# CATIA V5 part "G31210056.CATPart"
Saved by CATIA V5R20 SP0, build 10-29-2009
Part number: G31210056
Revision: 8
Definition: design
Nomenclature: G31210056
Source: made
Description: NOT SPECIFIED
Bounding box of the stored display mesh (mm): x -5 to 56, y -8 to 8, z -8 to 8
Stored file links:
  C:\Users\Raffaele\Desktop\3D X SITO CF\BOLEX\23-BUSH REF 312\G31210056.CATPart
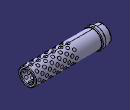
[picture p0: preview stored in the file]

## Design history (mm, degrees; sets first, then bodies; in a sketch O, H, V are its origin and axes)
Body1 "MANIFOLD_SOLID_BREP #12359" (main body)
  Solid1: solid without history
Body2 "MANIFOLD_SOLID_BREP #12502"
  Solid2: solid without history
Body3 "MANIFOLD_SOLID_BREP #12645"
  Solid3: solid without history
Body4 "MANIFOLD_SOLID_BREP #12788"
  Solid4: solid without history
Body5 "MANIFOLD_SOLID_BREP #12931"
  Solid5: solid without history
Body6 "MANIFOLD_SOLID_BREP #13076"
  Solid6: solid without history
Body7 "MANIFOLD_SOLID_BREP #13221"
  Solid7: solid without history
Body8 "MANIFOLD_SOLID_BREP #13366"
  Solid8: solid without history
Body9 "MANIFOLD_SOLID_BREP #13511"
  Solid9: solid without history
Body10 "MANIFOLD_SOLID_BREP #13656"
  Solid10: solid without history
Body11 "MANIFOLD_SOLID_BREP #13801"
  Solid11: solid without history
Body12 "MANIFOLD_SOLID_BREP #13946"
  Solid12: solid without history
Body13 "MANIFOLD_SOLID_BREP #14091"
  Solid13: solid without history
Body14 "MANIFOLD_SOLID_BREP #14236"
  Solid14: solid without history
Body15 "MANIFOLD_SOLID_BREP #14381"
  Solid15: solid without history
Body16 "MANIFOLD_SOLID_BREP #14526"
  Solid16: solid without history
Body17 "MANIFOLD_SOLID_BREP #14671"
  Solid17: solid without history
Body18 "MANIFOLD_SOLID_BREP #14816"
  Solid18: solid without history
Body19 "MANIFOLD_SOLID_BREP #14961"
  Solid19: solid without history
Body20 "MANIFOLD_SOLID_BREP #15106"
  Solid20: solid without history
Body21 "MANIFOLD_SOLID_BREP #15251"
  Solid21: solid without history
Body22 "MANIFOLD_SOLID_BREP #15396"
  Solid22: solid without history
Body23 "MANIFOLD_SOLID_BREP #15541"
  Solid23: solid without history
Body24 "MANIFOLD_SOLID_BREP #15686"
  Solid24: solid without history
Body25 "MANIFOLD_SOLID_BREP #15831"
  Solid25: solid without history
Body26 "MANIFOLD_SOLID_BREP #15976"
  Solid26: solid without history
Body27 "MANIFOLD_SOLID_BREP #16121"
  Solid27: solid without history
Body28 "MANIFOLD_SOLID_BREP #16266"
  Solid28: solid without history
Body29 "MANIFOLD_SOLID_BREP #16411"
  Solid29: solid without history
Body30 "MANIFOLD_SOLID_BREP #16556"
  Solid30: solid without history
Body31 "MANIFOLD_SOLID_BREP #16701"
  Solid31: solid without history
Body32 "MANIFOLD_SOLID_BREP #16846"
  Solid32: solid without history
Body33 "MANIFOLD_SOLID_BREP #16991"
  Solid33: solid without history
Body34 "MANIFOLD_SOLID_BREP #17136"
  Solid34: solid without history
Body35 "MANIFOLD_SOLID_BREP #17281"
  Solid35: solid without history
Body36 "MANIFOLD_SOLID_BREP #17424"
  Solid36: solid without history
Body37 "MANIFOLD_SOLID_BREP #17567"
  Solid37: solid without history
Body38 "MANIFOLD_SOLID_BREP #17712"
  Solid38: solid without history
Body39 "MANIFOLD_SOLID_BREP #17857"
  Solid39: solid without history
Body40 "MANIFOLD_SOLID_BREP #18002"
  Solid40: solid without history
Body41 "MANIFOLD_SOLID_BREP #18147"
  Solid41: solid without history
Body42 "MANIFOLD_SOLID_BREP #18292"
  Solid42: solid without history
Body43 "MANIFOLD_SOLID_BREP #18437"
  Solid43: solid without history
Body44 "MANIFOLD_SOLID_BREP #18582"
  Solid44: solid without history
Body45 "MANIFOLD_SOLID_BREP #18727"
  Solid45: solid without history
Body46 "MANIFOLD_SOLID_BREP #18872"
  Solid46: solid without history
Body47 "MANIFOLD_SOLID_BREP #19017"
  Solid47: solid without history
Body48 "MANIFOLD_SOLID_BREP #19162"
  Solid48: solid without history
Body49 "MANIFOLD_SOLID_BREP #19307"
  Solid49: solid without history
Body50 "MANIFOLD_SOLID_BREP #19452"
  Solid50: solid without history
Body51 "MANIFOLD_SOLID_BREP #19597"
  Solid51: solid without history
Body52 "MANIFOLD_SOLID_BREP #19742"
  Solid52: solid without history
Body53 "MANIFOLD_SOLID_BREP #19887"
  Solid53: solid without history
Body54 "MANIFOLD_SOLID_BREP #20032"
  Solid54: solid without history
Body55 "MANIFOLD_SOLID_BREP #20177"
  Solid55: solid without history
Body56 "MANIFOLD_SOLID_BREP #20322"
  Solid56: solid without history
Body57 "MANIFOLD_SOLID_BREP #20467"
  Solid57: solid without history
Body58 "MANIFOLD_SOLID_BREP #20610"
  Solid58: solid without history
Body59 "MANIFOLD_SOLID_BREP #20753"
  Solid59: solid without history
Body60 "MANIFOLD_SOLID_BREP #20898"
  Solid60: solid without history
Body61 "MANIFOLD_SOLID_BREP #21043"
  Solid61: solid without history
Body62 "MANIFOLD_SOLID_BREP #21188"
  Solid62: solid without history
Body63 "MANIFOLD_SOLID_BREP #21333"
  Solid63: solid without history
Body64 "MANIFOLD_SOLID_BREP #21478"
  Solid64: solid without history
Body65 "MANIFOLD_SOLID_BREP #21623"
  Solid65: solid without history
Body66 "MANIFOLD_SOLID_BREP #21766"
  Solid66: solid without history
Body67 "MANIFOLD_SOLID_BREP #21909"
  Solid67: solid without history
Body68 "MANIFOLD_SOLID_BREP #22054"
  Solid68: solid without history
Body69 "MANIFOLD_SOLID_BREP #22199"
  Solid69: solid without history
Body70 "MANIFOLD_SOLID_BREP #22344"
  Solid70: solid without history
Body71 "MANIFOLD_SOLID_BREP #22489"
  Solid71: solid without history
Body72 "MANIFOLD_SOLID_BREP #22634"
  Solid72: solid without history
Body73 "MANIFOLD_SOLID_BREP #22779"
  Solid73: solid without history
Body74 "MANIFOLD_SOLID_BREP #22924"
  Solid74: solid without history
Body75 "MANIFOLD_SOLID_BREP #23069"
  Solid75: solid without history
Body76 "MANIFOLD_SOLID_BREP #23214"
  Solid76: solid without history
Body77 "MANIFOLD_SOLID_BREP #23359"
  Solid77: solid without history
Body78 "MANIFOLD_SOLID_BREP #23504"
  Solid78: solid without history
Body79 "MANIFOLD_SOLID_BREP #23649"
  Solid79: solid without history
Body80 "MANIFOLD_SOLID_BREP #23794"
  Solid80: solid without history
Body81 "MANIFOLD_SOLID_BREP #23939"
  Solid81: solid without history
Body82 "MANIFOLD_SOLID_BREP #24084"
  Solid82: solid without history
Body83 "MANIFOLD_SOLID_BREP #24229"
  Solid83: solid without history
Body84 "MANIFOLD_SOLID_BREP #24374"
  Solid84: solid without history
Body85 "MANIFOLD_SOLID_BREP #24519"
  Solid85: solid without history
Body86 "MANIFOLD_SOLID_BREP #24664"
  Solid86: solid without history
Body87 "MANIFOLD_SOLID_BREP #24809"
  Solid87: solid without history
Body88 "MANIFOLD_SOLID_BREP #24952"
  Solid88: solid without history
Body89 "MANIFOLD_SOLID_BREP #25095"
  Solid89: solid without history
